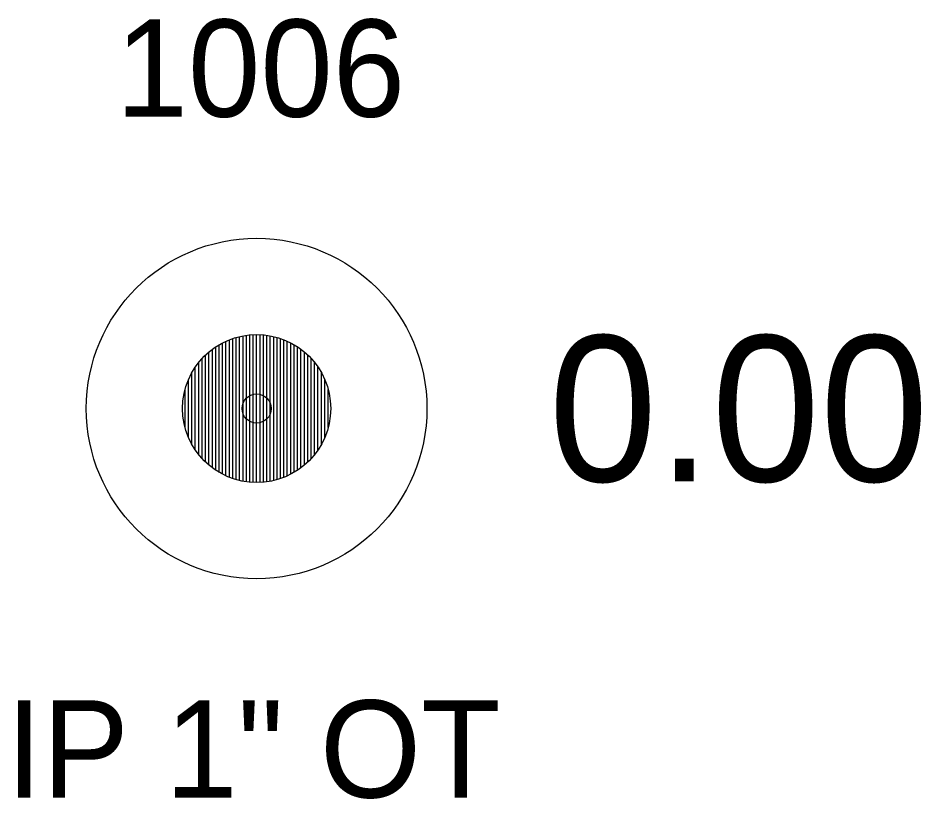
# Model space of a CAD drawing. Extents: x 1809463 to 1812121, y 790645 to 791946.
# Drawn here: x 1811886.29 to 1811895.56, y 790645.31 to 790653.34 of the extents above; entities that cross this region are included whole.
import ezdxf

# ---------------------------------------------------------------- set-up
doc = ezdxf.new("R2010")
doc.units = 0
for name, color, linetype in [('RD_EX_DV_Prop_txCode', 7, 'Continuous'), ('RD_EX_DV_PropPin', 7, 'Continuous'), ('RD_EX_TX_DV_Prop_ELEV', 7, 'Continuous'), ('RD_SMD_Locator', 7, 'Continuous')]:
    doc.layers.add(name, color=color, linetype=linetype)

msp = doc.modelspace()

# ---------------------------------------------------------------- linework, layer by layer
at = {"layer": 'RD_EX_DV_PropPin'}
for p, q in [((1811888.4927, 790648.6085), (1811888.4927, 790650.0495)), ((1811888.5277, 790648.5976), (1811888.5277, 790650.0604)), ((1811888.5627, 790648.5884), (1811888.5627, 790650.0696)), ((1811888.5977, 790648.581), (1811888.5977, 790650.077)), ((1811888.6327, 790648.5753), (1811888.6327, 790650.0827)), ((1811888.6678, 790648.5712), (1811888.6678, 790650.0868)), ((1811888.7028, 790648.5688), (1811888.7028, 790650.0892)), ((1811888.7378, 790648.568), (1811888.7378, 790650.09)), ((1811888.7728, 790648.5688), (1811888.7728, 790650.0892)), ((1811888.8078, 790648.5712), (1811888.8078, 790650.0868)), ((1811888.8428, 790648.5753), (1811888.8428, 790650.0827)), ((1811888.8778, 790648.581), (1811888.8778, 790650.077)), ((1811888.9128, 790648.5884), (1811888.9128, 790650.0696)), ((1811888.9479, 790648.5976), (1811888.9479, 790650.0604)), ((1811888.9829, 790648.6085), (1811888.9829, 790650.0495)), ((1811888.3176, 790648.6945), (1811888.3176, 790649.9635)), ((1811888.3526, 790648.6726), (1811888.3526, 790649.9854)), ((1811888.3876, 790648.6533), (1811888.3876, 790650.0047)), ((1811888.4227, 790648.6363), (1811888.4227, 790650.0217)), ((1811888.4577, 790648.6214), (1811888.4577, 790650.0366)), ((1811889.0179, 790648.6214), (1811889.0179, 790650.0366)), ((1811889.0529, 790648.6363), (1811889.0529, 790650.0217)), ((1811889.0879, 790648.6533), (1811889.0879, 790650.0047)), ((1811889.1229, 790648.6726), (1811889.1229, 790649.9854)), ((1811889.1579, 790648.6945), (1811889.1579, 790649.9635)), ((1811888.2126, 790648.7783), (1811888.2126, 790649.8797)), ((1811888.2476, 790648.7469), (1811888.2476, 790649.9111)), ((1811888.2826, 790648.7191), (1811888.2826, 790649.9389)), ((1811889.193, 790648.7191), (1811889.193, 790649.9389)), ((1811889.228, 790648.7469), (1811889.228, 790649.9111)), ((1811889.263, 790648.7783), (1811889.263, 790649.8797)), ((1811888.1425, 790648.8548), (1811888.1425, 790649.8032)), ((1811888.1776, 790648.8139), (1811888.1776, 790649.8441)), ((1811889.298, 790648.8139), (1811889.298, 790649.8441)), ((1811889.333, 790648.8548), (1811889.333, 790649.8032)), ((1811888.0725, 790648.9595), (1811888.0725, 790649.6985)), ((1811888.1075, 790648.9025), (1811888.1075, 790649.7555)), ((1811889.368, 790648.9025), (1811889.368, 790649.7555)), ((1811889.403, 790648.9595), (1811889.403, 790649.6985)), ((1811888.0375, 790649.0311), (1811888.0375, 790649.6269)), ((1811889.4381, 790649.0311), (1811889.4381, 790649.6269)), ((1811888.0025, 790649.1328), (1811888.0025, 790649.5252)), ((1811889.4731, 790649.1328), (1811889.4731, 790649.5252))]:
    msp.add_line(p, q, dxfattribs=at)
for radius in [1.75, 0.761]:
    msp.add_circle((1811888.7378, 790649.329), radius, dxfattribs=at)
at = {"layer": 'RD_SMD_Locator'}
msp.add_circle((1811888.7378, 790649.329), 0.15, dxfattribs=at)

# ---------------------------------------------------------------- texts
at = {"layer": 'RD_EX_DV_Prop_txCode'}
for s, p in [('1006', (1811887.289, 790652.329)), ('IP 1" OT', (1811886.163, 790645.329))]:
    msp.add_text(s, height=1, dxfattribs=at).set_placement(p)
at = {"layer": 'RD_EX_TX_DV_Prop_ELEV'}
msp.add_text('0.00', height=1.5, dxfattribs=at).set_placement((1811891.7378, 790648.579))

doc.saveas('drawing.dxf')
